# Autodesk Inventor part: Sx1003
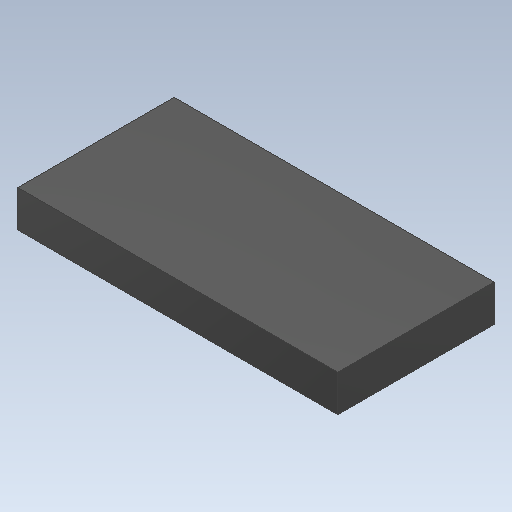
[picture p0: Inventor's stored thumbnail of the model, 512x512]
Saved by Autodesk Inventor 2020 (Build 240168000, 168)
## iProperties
Created: 2021-02
Part Number: Sx1003
Material: Generico
Document SubType Name: Modeling
Designer: zambolin
Density: 1 g/cm^3
Appearance: Default
Author: zambolin
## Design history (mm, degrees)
feature "Solido2"
node "Solido1"
